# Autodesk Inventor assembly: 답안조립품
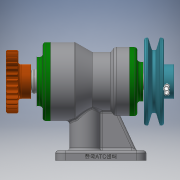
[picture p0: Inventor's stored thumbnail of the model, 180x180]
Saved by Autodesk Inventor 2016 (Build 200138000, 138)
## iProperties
Created: 2019-01
Part Number: 답안조립품
Material: 일반
Document SubType Name: Assembly
Designer: USER
Author: USER
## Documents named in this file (15)
- C:\Users\USER\Desktop\490107V1012\답안조립품.iam
- C:\Users\USER\Desktop\490107V1012\본체.ipt
- C:\Users\USER\Desktop\490107V1012\축.ipt
- C:\Users\USER\Desktop\490107V1012\키 6 x 6 x 18.ipt
- C:\Users\USER\Desktop\490107V1012\베어링 6205.ipt
- C:\Users\USER\Desktop\490107V1012\베어링 6203.ipt
- C:\Users\USER\Desktop\490107V1012\앞커버.ipt
- C:\Users\USER\Desktop\490107V1012\오일 실 25 38 8.ipt
- C:\Users\USER\Desktop\490107V1012\뒤커버.ipt
- C:\Users\USER\Desktop\490107V1012\오일 실 17 30 8.ipt
- C:\Users\USER\Desktop\490107V1012\키 5 x 5 x 20.ipt
- C:\Users\USER\Desktop\490107V1012\스퍼기어.ipt
- C:\Users\USER\Desktop\490107V1012\볼트 M4.ipt
- C:\Users\USER\Desktop\490107V1012\V-벨트풀리.ipt
- C:\Users\USER\Desktop\490107V1012\멈춤나사 M3.ipt
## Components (1 placed, 1 different names)
1. V-벨트풀리:1
